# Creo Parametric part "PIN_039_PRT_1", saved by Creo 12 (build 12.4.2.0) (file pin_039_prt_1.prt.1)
Units: Custom; MM, KILOGRAM, SECS

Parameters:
  PTC_WM_ITERATION = "0"
  PTC_WM_VERSION = "-.0"
  PTC_WM_LIFECYCLE_STATE = "In Work"
  PTC_WM_LIFECYCLE = "MO_CADDocument"
  PTC_WM_CREATED_BY = "Maximilian Roepper (Z0017RMS: MO)"
  PTC_WM_CREATED_ON = "18-Sep-26 11:36:42 AM"
  PTC_WM_MODIFIED_BY = "Maximilian Roepper (Z0017RMS: MO)"
  PTC_WM_MODIFIED_ON = "18-Sep-26 11:36:46 AM"
  PDMLINKNUMBER = "PDM000071454802"
  PTC_WM_NAME = "pin_039_prt_1.prt"
  PTC_WM_NUMBER = "PDM000071454802"

Other parameters: WEIGHT, WEIGHT_FACTOR, WEIGHT_ADD, _MASS_TEMP, _DIFF_TEMP, MC_ERRORS, SUPPLIER

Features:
  1. coordinate system
  2. datum plane "PRT_YZ"
  3. datum plane "PRT_XY"
  4. datum plane "PRT_XZ"
  5. coordinate system
  6. datum axis
  7. datum axis
  8. datum axis
  9. coordinate system
  10. imported feature
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
Other named items: PRT, SIEMENS_MO, DRW_VIEW_ORG, PRT_X, PRT_Y, PRT_Z, CS0, ROUGH_GROB

Layers: 00_STD_CSYS-KSYS, 01_STD_PLANES-EBENEN, 02_STD_AXES-ACHSEN, 03_STD_CSYS-KSYS, 24_IMPORT_FEAT-IMPORT_KE

Surfaces: 9 plane, 1 cylinder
